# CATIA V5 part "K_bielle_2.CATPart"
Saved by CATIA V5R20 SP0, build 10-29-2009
Part number: bielle_2
Publications: "Corps principal"
Bounding box of the stored display mesh (mm): x -40 to 40, y 76.001 to 257.079, z 181.053 to 254
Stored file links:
  G:\Khaled_CFAO_2011\ST2M\ST2M_GR2\echouteau\Khaled\CAD_ThinkMotion\K_bielle_2.CATPart
  F:\2A\Proj Think Motion\trainv3\Version3\sql_general.CATProduct
  G:\Khaled_CFAO_2011\ST2M\ST2M_GR2\echouteau\Khaled\CAD_ThinkMotion\K_bielle_1.CATPart
  G:\Khaled_CFAO_2011\ST2M\ST2M_GR2\echouteau\echouteau\bogie_beam.CATPart
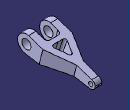
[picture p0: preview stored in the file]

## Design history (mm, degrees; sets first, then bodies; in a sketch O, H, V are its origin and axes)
Set1
  Point1: linked copy from another document
  Point2: linked copy from another document
Body1 (main body)
  Line1: type PtPt, FirstPoint Point1, SecondPoint Point2
  Plane1 "Plan_pivot": type Normal, Curve Line1, RefPoint Point2
  Line2: type PtDir, RefPoint Point2, Direction yz-plane, Start -209, End 0
  Plane2: type OffsetPt, RefPlane yz-plane, RefPoint vertex of Line2
  Line3: type PtDir, RefPoint Point1, Direction yz-plane, Start -209, End 0
  Plane3: type OffsetPt, RefPlane yz-plane, RefPoint vertex of Line3
  Plane4 "Plan.desquisse_bielle2": type 3Points, Element1 Point2, Element2 Point1, Element3 vertex of Line2
  Sketch1 on Plane4, origin (0, 147.2809, 217.9576), H (-1, 0, 0), V (0, -0.9691, 0.2468)
    point P1 (40, 77.7153)
    line L1 (40, 77.7153) -> (20, 77.7153)
    line L2 (40, 7.7153) -> (40, 77.7153)
    point P2 (-20, 77.7153)
    point P3 (0, -112.5218)
    line L3 (0, -112.5218) -> (9, -112.5218)
    point P4 (9, -112.5218)
    point P5 (0, 17.7153)
    point P6 (20, 77.7153)
    point P7 (-40, 77.7153)
    point P8 (0, -112.5218)
    line L4 (20, 77.7153) -> (20, 27.7153)
    point P9 (40, 7.7153)
    point P10 (9.5407, -57.5245)
    line L5 (10, 17.7153) -> (0, 17.7153)
    arc A1 centre (10, 27.7153) radius 10 from (10, 17.7153) to (20, 27.7153) ccw
    point P11 (10, 17.7153)
    point P12 (20, 27.7153)
    line L6 (9.5407, -57.5245) -> (9, -112.5218)
    line L7 (40, 7.7153) -> (9.5407, -57.5245)
    point P13 (-20, 27.7153)
    point P14 (-10, 17.7153)
    arc A2 centre (-10, 27.7153) radius 10 from (-10, 17.7153) to (-20, 27.7153) cw
    point P15 (0, 17.7153)
    line L8 (-10, 17.7153) -> (0, 17.7153)
    point P16 (-20, 77.7153)
    line L9 (-20, 77.7153) -> (-20, 27.7153)
    point P17 (-40, 77.7153)
    line L10 (-40, 77.7153) -> (-20, 77.7153)
    point P18 (-40, 7.7153)
    line L11 (-40, 7.7153) -> (-40, 77.7153)
    point P19 (-9.5407, -57.5245)
    line L12 (-40, 7.7153) -> (-9.5407, -57.5245)
    point P20 (-9, -112.5218)
    line L13 (-9.5407, -57.5245) -> (-9, -112.5218)
    point P21 (0, -112.5218)
    line L14 (0, -112.5218) -> (-9, -112.5218)
    distance P2 P6 = 40
    distance P7 P1 = 80
    distance P2 L8 = 60
    distance P9 P10 = 72
    distance P4 P3 = 9
    distance P19 P20 = 55
    distance P1 P9 = 70
    horizontal: L1 H, L3 H, L5 H
    vertical: L2 V, L4 V
    coincidence: P3 V, P5 V, P3 P8
    symmetry: P2 P6 V, P1 P7 V, P3 P8 V, P12 P13 V, P11 P14 V, A1 A2 V, P5 P15 V, L5 L8 V, P6 P16 V, L4 L9 V, P1 P17 V, L1 L10 V, P9 P18 V, L2 L11 V, P10 P19 V, L7 L12 V, P4 P20 V, L6 L13 V, P3 P21 V, L3 L14 V
    tangency: A1 L5, A1 L4
  Sketch2 on yz-plane, origin (0, 0, 0), H (0, 1, 0), V (0, 0, 1)
    arc A1 centre (245.0797, 193.0483) radius 12 from (242.1605, 181.4088) to (248.0841, 204.6661) ccw
    point P1 (245.0797, 193.0483)
    reference projected point E1 (245.0797, 193.0483) from Point1
    arc A2 centre (100, 230) radius 24 from (105.8461, 253.2771) to (93.9988, 206.7624) ccw
    point P2 (100, 230)
    reference projected point E2 (100, 230) from Point2
    line L1 (248.0841, 204.6661) -> (105.8461, 253.2771)
    line L2 (242.1605, 181.4088) -> (93.9988, 206.7624)
    coincidence: P1 E1, E2 P2
  SolidCombine1: FirstComponentProfile Sketch1, FirstComponentDirection Sketch1, SecondComponentProfile Sketch2, SecondComponentDirection Sketch2
  Sketch3 on zx-plane, origin (0, 0, 0), H (-1, 0, 0), V (0, 0, 1)
    point P1 (0, 30.5941)
    point P2 (36.1655, 29.1213)
    line L1 (36.1655, 29.1213) -> (36.1655, 112.5339)
    point P3 (36.1655, 112.5339)
    line L2 (36.1655, 112.5339) -> (7, 112.5339)
    point P4 (7, 112.5339)
    line L3 (7, 112.5339) -> (7, 42)
    line L4 (3, 38) -> (0, 38)
    point P5 (0, 38)
    point P6 (0, 38)
    line L5 (-3, 38) -> (0, 38)
    point P7 (-7, 112.5339)
    line L6 (-7, 112.5339) -> (-7, 42)
    point P8 (-36.1655, 112.5339)
    line L7 (-36.1655, 112.5339) -> (-7, 112.5339)
    point P9 (-36.1655, 29.1213)
    line L8 (-36.1655, 29.1213) -> (-36.1655, 112.5339)
    point P10 (0, 30.5941)
    arc A1 centre (3, 42) radius 4 from (7, 42) to (3, 38) cw
    arc A2 centre (-3, 42) radius 4 from (-7, 42) to (-3, 38) ccw
    reference projected curve E1
    line L9 (-36.1655, 29.1213) -> (36.1655, 29.1213)
    radius A1 = 4
    radius A2 = 4
    distance P4 P7 = 14
    coincidence: P1 V, P5 V, P1 P10, P5 P6, P9 E1
    vertical: L1 V, L3 V
    horizontal: L2 H, L4 H, L9 H
    symmetry: P5 P6 V, L4 L5 V, P4 P7 V, L3 L6 V, P3 P8 V, L2 L7 V, P2 P9 V, L1 L8 V, P1 P10 V
    tangency: A1 L3, A1 L4, A2 L6, A2 L5
  Sketch4 on face of SolidCombine1 from Sketch1.L11, origin (40, 105.7292, 240.1517), H (0, 1, 0), V (0, 0, 1)
    point P1 (-5.7292, -10.1517)
    reference projected arc E1 centre (-5.7292, -10.1517) radius 24 from (0.1168, 13.1253) to (-11.7304, -33.3893) ccw from edge [face of SolidCombine1 from Sketch2.A2 | face of SolidCombine1 from Sketch1.L11]
    concentricity: P1 E1
  Hole1: placed by Sketch4, at (40, 100, 230) direction (-1, 0, 0), diameter 25, up to face of SolidCombine1 from Sketch1.L2
  Sketch5 on face of SolidCombine1 from Sketch1.L13, origin (9.0395, 253.4079, 195.0309), H (0.0098, -0.969, 0.2468), V (0, -0.2468, -0.9691)
    point P1 (7.5816, 3.9768)
    reference projected curve E1 from edge [face of SolidCombine1 from Sketch1.L13 | face of SolidCombine1 from Sketch2.A1]
    concentricity: P1 E1
  Hole2: placed by Sketch5, at (9.1141, 245.0797, 193.0483) direction (-1, -0.0095, 0.0024), diameter 12, up to face of SolidCombine1 from Sketch1.L6
  Sketch6 on face of SolidCombine1 from Sketch2.L1, origin (0, 248.0841, 204.6661), H (0, -0.9463, 0.3234), V (1, 0, 0)
    line L1 (107, 13.1581) -> (107, 0)
    point P1 (107, 0)
    point P2 (107, 21)
    line L2 (99.8903, 17.6912) -> (71.6172, 4.5331)
    point P3 (61.8767, 0)
    reference projected line E1 (109.0284, 40) -> (43.5797, 9.5407) from edge [face of SolidCombine1 from Sketch1.L12 | face of SolidCombine1 from Sketch2.L1]
    point P4 (61.8767, 0)
    point P5 (107, -21)
    line L3 (99.8903, -17.6912) -> (71.6172, -4.5331)
    point P6 (107, 0)
    line L4 (107, -13.1581) -> (107, 0)
    reference projected line E2 (119.0605, 0) -> (119.0605, 10) from edge [face of SolidCombine1 from Sketch1.L8 | face of SolidCombine1 from Sketch2.L1]
    arc A1 centre (73.7268, 0) radius 5 from (71.6172, 4.5331) to (71.6172, -4.5331) ccw
    arc A2 centre (102, 13.1581) radius 5 from (99.8903, 17.6912) to (107, 13.1581) cw
    arc A3 centre (102, -13.1581) radius 5 from (99.8903, -17.6912) to (107, -13.1581) ccw
    radius A1 = 5
    distance P2 P1 = 21
    radius A2 = 5
    radius A3 = 5
    coincidence: P1 H, P3 H, P1 P6, P3 P4, L2 P3, L3 P4, L2 P2, L1 P2, L3 P5, L4 P5
    vertical: L1 V
    parallelism: E1 L2, L1 E2
    symmetry: P3 P4 H, P2 P5 H, L2 L3 H, P1 P6 H, L1 L4 H
    tangency: A1 L2, A1 L3, A2 L2, A2 L1, A3 L3, A3 L4
  Pocket1: profile Sketch6, direction along face of SolidCombine1 from Sketch2.L1 reversed, through (limit type 3)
